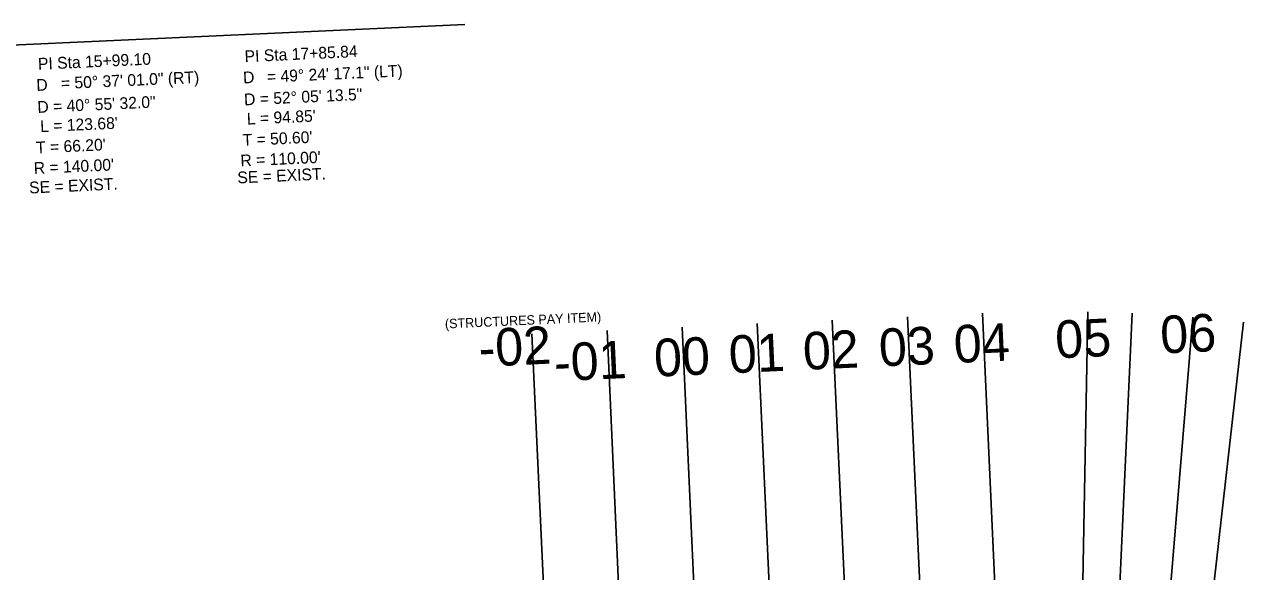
# Model space of a CAD drawing. Extents: x 1191189 to 1191812, y 892693 to 893370.
# Drawn here: x 1191327.5 to 1191587, y 893126.5 to 893242.9 of the extents above; entities that cross this region are included whole.
import ezdxf

# ---------------------------------------------------------------- set-up
doc = ezdxf.new("R2010")
doc.units = 0
for name, color, linetype in [('Default', 7, 'Continuous'), ('Prop Horizontal Alignment Curve and Spiral Data', 7, 'Continuous'), ('Scratch_Level_1', 7, 'Continuous')]:
    doc.layers.add(name, color=color, linetype=linetype)

msp = doc.modelspace()

# ---------------------------------------------------------------- linework, layer by layer
at = {"layer": 'Prop Horizontal Alignment Curve and Spiral Data'}
msp.add_line((1191188.94, 893232.25), (1191421.22, 893242.88), dxfattribs=at)
at = {"layer": 'Scratch_Level_1'}
for p, q in [((1191515.42, 893180.69), (1191524.56, 892980.9)), ((1191531.4, 893181.42), (1191540.54, 892981.63)), ((1191531.4, 893181.42), (1191540.54, 892981.63)), ((1191553.79, 893181.72), (1191550.14, 892981.76)), ((1191563.25, 893181.42), (1191554.19, 892981.63)), ((1191576.16, 893180.6), (1191559.72, 892981.28)), ((1191451.48, 893177.76), (1191456.05, 893077.87)), ((1191467.47, 893178.49), (1191472.04, 893078.6)), ((1191483.45, 893179.22), (1191488.02, 893079.33)), ((1191499.43, 893179.96), (1191508.57, 892980.16)), ((1191586.97, 893179.54), (1191564.36, 892980.82)), ((1191435.5, 893177.03), (1191440.07, 893077.13))]:
    msp.add_line(p, q, dxfattribs=at)

# ---------------------------------------------------------------- texts
at = {"layer": 'Default'}
msp.add_text('(STRUCTURES PAY ITEM)', height=2, rotation=2.6195, dxfattribs=at).set_placement((1191417.03, 893178.18))
at = {"layer": 'Prop Horizontal Alignment Curve and Spiral Data'}
for s, p in [('PI Sta 17+85.84', (1191374.4, 893234.84)), ('PI Sta 15+99.10', (1191330.42, 893233.23)), ('= 50%%d 37\' 01.0" (RT)', (1191335.31, 893229.11)), ('D', (1191374.07, 893230.32)), ('= 49%%d 24\' 17.1" (LT)', (1191379.16, 893230.5)), ('D', (1191330.08, 893228.72)), ('D = 40%%d 55\' 32.0"', (1191330.3, 893224.04)), ('D = 52%%d 05\' 13.5"', (1191374.28, 893225.65)), ("L = 94.85'", (1191374.88, 893221.55)), ("L = 123.68'", (1191330.9, 893219.95)), ("T = 50.60'", (1191373.99, 893217.02)), ("T = 66.20'", (1191330.01, 893215.42)), ("R = 140.00'", (1191329.53, 893211.05)), ("R = 110.00'", (1191373.51, 893212.65)), ('SE = EXIST.', (1191372.86, 893209.04)), ('SE = EXIST.', (1191328.55, 893206.9))]:
    msp.add_text(s, height=2.5, rotation=2.621, dxfattribs=at).set_placement(p)
at = {"layer": 'Scratch_Level_1'}
for s, p in [('05', (1191547.06, 893171.83)), ('06', (1191569.41, 893172.85)), ('-02', (1191424.31, 893170.02)), ('02', (1191493.36, 893169.37)), ('03', (1191509.53, 893170.11)), ('04', (1191525.47, 893170.84)), ('-01', (1191440.37, 893166.95)), ('00', (1191461.67, 893167.92)), ('01', (1191477.58, 893168.65))]:
    msp.add_text(s, height=8, rotation=2.6614, dxfattribs=at).set_placement(p)

doc.saveas('drawing.dxf')
